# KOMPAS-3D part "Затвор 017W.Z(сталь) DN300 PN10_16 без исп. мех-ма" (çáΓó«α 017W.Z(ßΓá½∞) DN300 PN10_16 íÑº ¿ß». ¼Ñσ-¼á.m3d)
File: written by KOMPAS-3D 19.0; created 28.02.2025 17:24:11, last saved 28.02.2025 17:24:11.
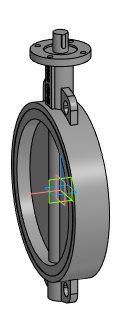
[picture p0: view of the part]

Document properties: Автор: Евгений; Полное имя файла: E:\Dendor Работа Сачек\3D для проекитирвщиков\1.5 Тип 017W.Z Сталь Затвор дисковый поворотный Межфланцевый\stp_Тип 017W.Z(сталь). Затвор без исполн. механизма\Затвор 017W.Z(сталь) DN300 PN10_16 без исп. мех-ма.m3d

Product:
- Part/product: Затвор 017W.Z(сталь) DN300 PN10_16 без исп. мех-ма

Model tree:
1. Операция без истории:1  (labels: Затвор 017W.Z(сталь) DN300 PN10_16 без исп. мех-ма)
